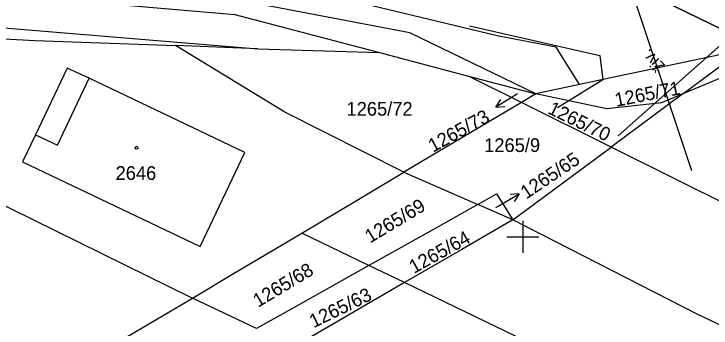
# Model space of a CAD drawing. Extents: x -779302 to -774398, y -1144902 to -1142831.
# Drawn here: x -777063.2 to -776976.6, y -1143911.3 to -1143872.3 of the extents above; entities that cross this region are included whole.
import ezdxf

# ---------------------------------------------------------------- set-up
doc = ezdxf.new("R2010")
doc.units = 0
for name, color, linetype in [('hektosit - Vrstva 5', 7, 'Continuous'), ('Hranice parcel', 7, 'Continuous'), ('legenda I_5_2 - Vrstva 53', 7, 'Continuous'), ('Parcelní čísla', 7, 'Continuous'), ('Pop  PČ popisy', 7, 'Continuous'), ('SŽDC', 7, 'Continuous'), ('Vnitřní kresba', 7, 'Continuous'), ('zjednodus_g_situ-seda - Vrstva 25', 7, 'Continuous'), ('zjednodus_g_situ-seda - Vrstva 51', 7, 'Continuous'), ('Značky budov', 7, 'Continuous')]:
    doc.layers.add(name, color=color, linetype=linetype)

msp = doc.modelspace()

# ---------------------------------------------------------------- linework, layer by layer
at = {"layer": 'hektosit - Vrstva 5'}
for p, q in [((-777000, -1143898), (-777000, -1143902)), ((-777002, -1143900), (-776998, -1143900))]:
    msp.add_line(p, q, dxfattribs=at)
at = {"layer": 'Hranice parcel'}
for p, q in [((-777032.92, -1143876.65), (-777043.14, -1143876.21)), ((-777032.92, -1143876.65), (-777017.82, -1143877.1)), ((-776980.14, -1143882.23), (-776972.79, -1143876.78)), ((-777017.82, -1143877.1), (-777006.74, -1143880.02)), ((-777006.74, -1143880.02), (-776998.39, -1143882.22)), ((-777000.18, -1143883.29), (-777006.74, -1143880.02)), ((-776998.39, -1143882.22), (-777000.18, -1143883.29)), ((-776980.14, -1143882.23), (-776989.05, -1143888.84)), ((-777000.18, -1143883.29), (-777014.77, -1143891.96)), ((-776989.05, -1143888.84), (-777000.18, -1143883.29)), ((-777001.23, -1143897.87), (-776989.05, -1143888.84)), ((-777014.77, -1143891.96), (-777005.59, -1143895.97)), ((-777001.23, -1143897.87), (-777005.59, -1143895.97)), ((-777019.12, -1143903.55), (-777027.46, -1143899.52)), ((-777014.7, -1143905.69), (-777019.12, -1143903.55)), ((-777033.09, -1143911.38), (-777041.02, -1143907.6))]:
    msp.add_line(p, q, dxfattribs=at)
for points in [[(-776998.39, -1143882.22), (-777014.02, -1143874.66), (-777035.36, -1143870.54), (-777167.58, -1143858.82), (-777281.88, -1143848.9), (-777289.53, -1143848.43), (-777292.27, -1143847.75), (-777303.16, -1143845.03)], [(-777211.92, -1143858.84), (-777211.13, -1143856.84), (-777167.5, -1143860.96), (-777150.77, -1143862.48), (-777035.76, -1143872.38), (-777017.82, -1143877.1)], [(-777002.25, -1143861.05), (-776982.48, -1143870.69), (-776970.83, -1143876.37)], [(-777124.98, -1143869.13), (-777082.45, -1143872.54), (-777032.92, -1143876.65)], [(-777110.44, -1143872.81), (-777100.29, -1143878.41), (-777041.02, -1143907.6)], [(-777110.44, -1143872.81), (-777098.28, -1143873.49), (-777074.51, -1143874.84), (-777060.56, -1143875.59), (-777043.14, -1143876.21)], [(-777014.77, -1143891.96), (-777029.58, -1143884.49), (-777043.14, -1143876.21)], [(-776972.79, -1143876.78), (-776992.99, -1143881.07), (-776998.39, -1143882.22)], [(-777053.88, -1143880.29), (-777056.58, -1143879.03), (-777060.52, -1143887.31), (-777062.13, -1143890.66), (-777040.08, -1143901.18), (-777034.53, -1143889.5), (-777053.88, -1143880.29)], [(-776964.5, -1143886.48), (-776975.37, -1143880.22), (-776980.14, -1143882.23)], [(-776980.14, -1143882.23), (-776982.79, -1143883.35), (-776989.59, -1143884.09), (-776998.39, -1143882.22)], [(-776817.86, -1143983.94), (-776814.26, -1143974.07), (-776869.06, -1143948.13), (-776905.56, -1143930.42), (-776989.05, -1143888.84)], [(-777027.46, -1143899.52), (-777020.38, -1143895.3), (-777014.77, -1143891.96)], [(-777005.59, -1143895.97), (-777003.26, -1143894.66), (-777001.23, -1143897.87)], [(-777005.59, -1143895.97), (-777011.86, -1143899.48), (-777019.12, -1143903.55)], [(-777001.23, -1143897.87), (-777007.6, -1143901.57), (-777014.7, -1143905.69)], [(-776819.3, -1143987.88), (-776871.91, -1143959.94), (-776915.87, -1143938.7), (-776942.03, -1143926.84), (-776978.29, -1143909.65), (-777001.23, -1143897.87)], [(-777041.02, -1143907.6), (-777036.15, -1143904.69), (-777027.46, -1143899.52)], [(-777019.12, -1143903.55), (-777028.04, -1143908.55), (-777033.09, -1143911.38)], [(-777014.7, -1143905.69), (-777023.42, -1143910.75), (-777028.37, -1143913.63)], [(-776828.14, -1143996.73), (-776887.84, -1143965.39), (-776966.84, -1143928.84), (-777014.7, -1143905.69)], [(-777057.27, -1143917.26), (-777050.08, -1143912.98), (-777041.02, -1143907.6)]]:
    msp.add_lwpolyline(points, dxfattribs=at)
at = {"layer": 'legenda I_5_2 - Vrstva 53'}
msp.add_lwpolyline([(-776893.47, -1143907.54), (-776959.34, -1143880.62), (-776970.83, -1143876.37), (-776982.48, -1143870.69)], dxfattribs=at)
at = {"layer": 'Pop  PČ popisy'}
for p, q in [((-777000.78, -1143882.32), (-777003.352, -1143883.866)), ((-777000.66, -1143882.24), (-777000.78, -1143882.32)), ((-777003.352, -1143883.866), (-777002.752, -1143882.921)), ((-777003.352, -1143883.866), (-777002.236, -1143883.779)), ((-777003.05, -1143896.19), (-777000.478, -1143894.644)), ((-777000.478, -1143894.644), (-777001.594, -1143894.731)), ((-777000.478, -1143894.644), (-777001.078, -1143895.589)), ((-777003.35, -1143896.37), (-777003.05, -1143896.19))]:
    msp.add_line(p, q, dxfattribs=at)
at = {"layer": 'SŽDC'}
msp.add_lwpolyline([(-776098.59, -1144230.98), (-776104.51, -1144228.21), (-776116.08, -1144223.44), (-776126.28, -1144219.86), (-776203.96, -1144186.83), (-776252.27, -1144167.08), (-776325.22, -1144137.73), (-776342.13, -1144130.92), (-776434.38, -1144092.81), (-776527.2, -1144055.02), (-776604.66, -1144024.21), (-776606.85, -1144023.34), (-776609.89, -1144021.72), (-776627.91, -1144012.39), (-776712.36, -1143980.08), (-776747.29, -1143966.09), (-776893.47, -1143907.54), (-776959.34, -1143880.62), (-776970.83, -1143876.37), (-776982.48, -1143870.69)], dxfattribs=at)
at = {"layer": 'Vnitřní kresba'}
for p, q in [((-777003.19, -1143875), (-777027.55, -1143869.14)), ((-776995.85, -1143876.42), (-777003.19, -1143875)), ((-776992.99, -1143881.07), (-776995.85, -1143876.42)), ((-777057.81, -1143888.59), (-777053.88, -1143880.29)), ((-777060.52, -1143887.31), (-777057.81, -1143888.59))]:
    msp.add_line(p, q, dxfattribs=at)
at = {"layer": 'zjednodus_g_situ-seda - Vrstva 25'}
msp.add_line((-776999.526, -1143830.236), (-776979.076, -1143891.736), dxfattribs=at)
at = {"layer": 'zjednodus_g_situ-seda - Vrstva 51'}
for points in [[(-776988.15, -1143887.443), (-776971.771, -1143872.888), (-776968.131, -1143870.95), (-776966.353, -1143869.925), (-776965.024, -1143868.815), (-776963.996, -1143869.422), (-776960.291, -1143864.078), (-776957.645, -1143859.629), (-776954.186, -1143849.739), (-776952.22, -1143844.266)], [(-777006.632, -1143873.761), (-776990.458, -1143877.442), (-776990.068, -1143880.5), (-776995.707, -1143883.958)]]:
    msp.add_lwpolyline(points, dxfattribs=at)
at = {"layer": 'Značky budov'}
msp.add_circle((-777047.987, -1143888.919), 0.175, dxfattribs=at)

# ---------------------------------------------------------------- texts
at = {"layer": 'Parcelní čísla'}
for s, rotation, p in [('1265/71', 11, (-776988.414, -1143883.844)), ('1265/70', 334, (-776997.033, -1143884.595)), ('1265/73', 29, (-777011.159, -1143889.559)), ('1265/65', 34, (-776999.575, -1143895.366)), ('1265/69', 31, (-777018.982, -1143900.838)), ('1265/64', 29, (-777013.537, -1143904.613)), ('1265/68', 31, (-777032.882, -1143908.818)), ('1265/63', 26, (-777025.997, -1143911.363))]:
    msp.add_text(s, height=1.7, rotation=rotation, dxfattribs=at).set_placement(p)
for s, p in [('1265/72', (-777021.91, -1143884.94)), ('1265/9', (-777004.81, -1143889.453)), ('2646', (-777050.59, -1143892.92))]:
    msp.add_text(s, height=1.7, dxfattribs=at).set_placement(p)
at = {"layer": 'zjednodus_g_situ-seda - Vrstva 51'}
msp.add_text('živ.', height=1.5, rotation=134.37366, dxfattribs=at).set_placement((-776982.258, -1143878.679))

doc.saveas('drawing.dxf')
